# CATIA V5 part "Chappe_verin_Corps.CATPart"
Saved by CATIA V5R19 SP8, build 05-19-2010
Part number: Chappe_verin
Nomenclature: 38-c
Material "Acier": density 7860 kg/m3, Young's modulus 2e+11 Pa, Poisson ratio 0.266, thermal expansion 1.17e-05 1/K
Bounding box of the stored display mesh (mm): x -7.996 to 7.996, y -6.277 to 6.277, z 0 to 24
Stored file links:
  C:\Users\rphgr\Desktop\0_Tapis_TC520B_vitesse\Chappe_verin_Corps.CATPart
  D:\Programmes\DassaultSysteme\win_b64\reffiles\standard\MetricThickPitch.txt
  D:\Programmes\DassaultSysteme\win_b64\startup\materials\French\Catalog.CATMaterial
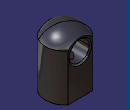
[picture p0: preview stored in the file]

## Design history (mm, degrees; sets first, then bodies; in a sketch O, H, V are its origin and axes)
AxisSystem1: origin (0, 0, 0), X (1, 0, 0), Y (0, 1, 0), Z (0, 0, 1)
Body1 (main body), material "Acier"
  Sketch1 on XY plane of AxisSystem1, origin (0, 0, 0), H (1, 0, 0), V (0, 1, 0)
    arc A1 centre (0, 0) radius 8 from (-4.9593, 6.2774) to (-4.9593, -6.2774) ccw
    line L1 (4.9593, -6.2774) -> (-4.9593, -6.2774)
    line L2 (-4.9593, 6.2774) -> (4.9593, 6.2774)
    point P4 (4.9593, -6.2774)
    arc A2 centre (0, 0) radius 8 from (4.9593, -6.2774) to (4.9593, 6.2774) ccw
    radius A1 = 8
    distance L1 L2 = 12.5548
    horizontal: L1 H, L2 H
    equidistance: L1 L2 O
    coincidence: A1 P4, A1 A2
  Pad1: profile Sketch1, direction (0, 0, 1), length 24
  Sketch2 on ZX plane of AxisSystem1, origin (0, 0, 0), H (0, 0, 1), V (1, 0, 0)
    arc A1 centre (15.1, 0) radius 8.9 from (24, 0) to (19, 8) ccw
    point P1 (15.1, 0)
    point P2 (24, 0)
    point P3 (19, 8)
    reference intersected line E1 (24, 8) -> (24, -8) from end face of Pad1
    reference intersected line E2 (24, 8) -> (24, -8) from end face of Pad1
    reference projected line E3 through (0, 0) direction (1, 0) from edge [ZX plane of AxisSystem1 | YZ plane of AxisSystem1]
    distance P3 E2 = 5
    distance P3 E3 = 8
    coincidence: P1 H, P2 H, P2 E1
  Groove1: profile Sketch2, axis Z axis, angle 360
  Sketch3 on face of Pad1 from Sketch1.L2, origin (0, 6.2774, 0), H (-1, 0, 0), V (0, 0, 1)
    circle A1 centre (0, 16.2518) radius 4.1
    point P1 (0, 16.2518)
    radius A1 = 4.1
    coincidence: P1 V
  Pocket1: profile Sketch3, direction (0, -1, 0), through (limit type 3)
  Chamfer1: length 0.5, angle 45, on edge [face of Pad1 from Sketch1.L2 | face of Pocket1 from Sketch3.A1]; edge [face of Pocket1 from Sketch3.A1 | face of Pad1 from Sketch1.L1]
  Sketch4 on start face of Pad1, origin (-1.3772, 0.3797, 0), H (1, 0, 0), V (0, -1, 0)
    point P1 (1.3772, 0.3797)
    reference projected point E1 (1.3772, 0.3797) from vertex [YZ plane of AxisSystem1 | ZX plane of AxisSystem1 | XY plane of AxisSystem1]
    coincidence: P1 E1
  Hole1: placed by Sketch4, at (0, 0, 0) direction (0, 0, 1), diameter 6.647, depth 12, V-bottom angle 120, threaded "M8", thread diameter 8, thread depth 10, pitch 1.25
